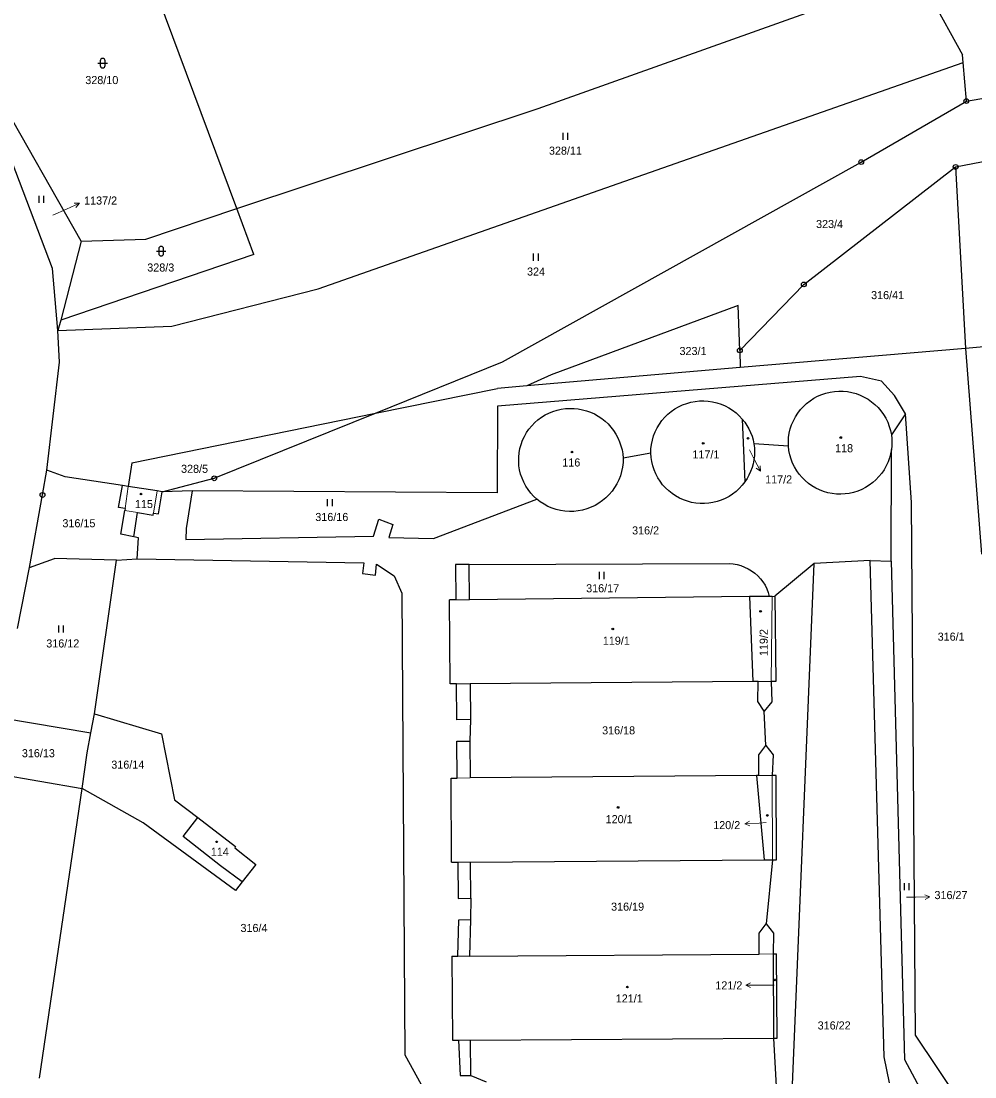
# Model space of a CAD drawing. Extents: x -765428 to -762163, y -1107632 to -1104975.
# Drawn here: x -763891.8 to -763690.9, y -1106861.1 to -1106638.7 of the extents above; entities that cross this region are included whole.
import ezdxf
from ezdxf.enums import TextEntityAlignment as Align

# ---------------------------------------------------------------- set-up
doc = ezdxf.new("R2010")
doc.units = 0
doc.header["$LTSCALE"] = 0.68
for name, color, linetype, lineweight in [('1', 7, 'Continuous', 25), ('3', 7, 'Continuous', 25), ('4', 7, 'Continuous', 13), ('5', 7, 'Continuous', 25), ('7', 7, 'Continuous', 13), ('8', 7, 'Continuous', 25)]:
    doc.layers.add(name, color=color, linetype=linetype, lineweight=lineweight)
doc.layers.add('2', color=7, linetype='Continuous')

msp = doc.modelspace()

# ---------------------------------------------------------------- linework, layer by layer
at = {"layer": '1'}
for p, q in [((-763846.36, -1106678.16), (-763869.74, -1106615.24)), ((-763782.87, -1106657.13), (-763702.97, -1106628.58)), ((-763702.97, -1106628.58), (-763693.52, -1106645.81)), ((-763885.2, -1106690.82), (-763903.89, -1106641.54)), ((-763879.14, -1106685.04), (-763903.89, -1106641.54)), ((-763693.39, -1106647.39), (-763693.52, -1106645.81)), ((-763770.01, -1106674.28), (-763693.39, -1106647.39)), ((-763692.69, -1106655.53), (-763693.39, -1106647.39)), ((-763692.69, -1106655.53), (-763674.07, -1106652.31)), ((-763714.83, -1106668.38), (-763692.69, -1106655.53)), ((-763846.36, -1106678.16), (-763782.87, -1106657.13)), ((-763694.94, -1106669.4), (-763676.21, -1106665.73)), ((-763790.41, -1106710.49), (-763714.83, -1106668.38)), ((-763726.92, -1106694.15), (-763694.94, -1106669.4)), ((-763694.94, -1106669.4), (-763692.84, -1106707.64)), ((-763829.2, -1106695.08), (-763770.01, -1106674.28)), ((-763865.55, -1106684.6), (-763846.36, -1106678.16)), ((-763842.75, -1106687.87), (-763846.36, -1106678.16)), ((-763879.14, -1106685.04), (-763865.55, -1106684.6)), ((-763879.14, -1106685.04), (-763883.43, -1106701.69)), ((-763842.75, -1106687.87), (-763883.43, -1106701.69)), ((-763884.08, -1106703.87), (-763885.2, -1106690.82)), ((-763860.01, -1106702.92), (-763829.2, -1106695.08)), ((-763740.4, -1106708.05), (-763726.92, -1106694.15)), ((-763740.75, -1106698.63), (-763780.11, -1106713.2)), ((-763740.4, -1106708.05), (-763740.75, -1106698.63)), ((-763883.43, -1106701.69), (-763884.08, -1106703.87)), ((-763884.08, -1106703.87), (-763860.01, -1106702.92)), ((-763883.68, -1106710.5), (-763884.08, -1106703.87)), ((-763684.15, -1106706.9), (-763692.84, -1106707.64)), ((-763740.4, -1106708.05), (-763740.31, -1106711.69)), ((-763692.84, -1106707.64), (-763740.31, -1106711.69)), ((-763692.84, -1106707.64), (-763689.53, -1106750.98)), ((-763886.36, -1106733.29), (-763883.68, -1106710.5)), ((-763817.15, -1106721.29), (-763790.41, -1106710.49)), ((-763714.95, -1106713.54), (-763791.44, -1106719.8)), ((-763740.31, -1106711.69), (-763785.28, -1106715.53)), ((-763780.11, -1106713.2), (-763785.28, -1106715.53)), ((-763710.56, -1106714.54), (-763714.95, -1106713.54)), ((-763817.15, -1106721.29), (-763791.43, -1106716.05)), ((-763785.28, -1106715.53), (-763791.43, -1106716.05)), ((-763707.84, -1106717.56), (-763710.56, -1106714.54)), ((-763705.49, -1106721.4), (-763707.84, -1106717.56)), ((-763791.44, -1106719.8), (-763791.48, -1106738.03)), ((-763868.45, -1106731.77), (-763817.15, -1106721.29)), ((-763851.1, -1106735), (-763817.15, -1106721.29)), ((-763739.88, -1106722.51), (-763739.35, -1106735.76)), ((-763705.49, -1106721.4), (-763708.48, -1106725.85)), ((-763704.22, -1106740.09), (-763705.49, -1106721.4)), ((-763730.16, -1106728.26), (-763737.42, -1106727.74)), ((-763708.52, -1106752.45), (-763708.47, -1106728.92)), ((-763759.16, -1106729.68), (-763764.98, -1106730.77)), ((-763887.28, -1106738.51), (-763886.36, -1106733.29)), ((-763882.5, -1106734.7), (-763886.36, -1106733.29)), ((-763868.45, -1106731.77), (-763869.21, -1106736.7)), ((-763870.45, -1106736.5), (-763882.5, -1106734.7)), ((-763862.05, -1106737.83), (-763851.1, -1106735)), ((-763871.26, -1106741.15), (-763870.45, -1106736.5)), ((-763869.21, -1106736.7), (-763870.45, -1106736.5)), ((-763863.13, -1106737.66), (-763869.21, -1106736.7)), ((-763862.05, -1106737.83), (-763863.13, -1106737.66)), ((-763862.87, -1106742.47), (-763862.05, -1106737.83)), ((-763855.75, -1106737.61), (-763862.05, -1106737.83)), ((-763855.75, -1106737.61), (-763857.03, -1106745.58)), ((-763791.48, -1106738.03), (-763855.75, -1106737.61)), ((-763890.05, -1106753.82), (-763887.28, -1106738.51)), ((-763804.89, -1106747.65), (-763783.17, -1106739.4)), ((-763703.4, -1106852.31), (-763704.22, -1106740.09)), ((-763869.88, -1106741.38), (-763871.26, -1106741.15)), ((-763870.76, -1106746.8), (-763869.95, -1106741.8)), ((-763869.88, -1106741.38), (-763869.95, -1106741.8)), ((-763868.05, -1106747.36), (-763867.28, -1106742.22)), ((-763867.28, -1106742.22), (-763863.98, -1106742.73)), ((-763863.98, -1106742.73), (-763863.91, -1106742.32)), ((-763863.91, -1106742.32), (-763862.87, -1106742.47)), ((-763817.54, -1106747.22), (-763816.46, -1106743.64)), ((-763816.46, -1106743.64), (-763813.52, -1106744.71)), ((-763813.52, -1106744.71), (-763814.34, -1106747.44)), ((-763868.05, -1106747.36), (-763870.76, -1106746.8)), ((-763857.03, -1106745.58), (-763857.08, -1106747.91)), ((-763857.08, -1106747.91), (-763817.54, -1106747.22)), ((-763867.03, -1106747.52), (-763868.05, -1106747.36)), ((-763867.36, -1106751.98), (-763867.03, -1106747.52)), ((-763814.34, -1106747.44), (-763804.89, -1106747.65)), ((-763892.53, -1106766.67), (-763890.05, -1106753.82)), ((-763890.05, -1106753.82), (-763884.76, -1106751.91)), ((-763871.69, -1106752.24), (-763884.76, -1106751.91)), ((-763876.32, -1106784.62), (-763871.69, -1106752.24)), ((-763871.69, -1106752.24), (-763867.36, -1106751.98)), ((-763867.36, -1106751.98), (-763819.63, -1106752.8)), ((-763819.63, -1106752.8), (-763819.89, -1106755.07)), ((-763817.17, -1106755.38), (-763816.91, -1106753.11)), ((-763816.91, -1106753.11), (-763813.24, -1106755.54)), ((-763797.42, -1106753.13), (-763800.32, -1106753.16)), ((-763800.32, -1106753.16), (-763800.25, -1106760.62)), ((-763797.42, -1106753.13), (-763742.64, -1106752.98)), ((-763797.35, -1106760.58), (-763797.42, -1106753.13)), ((-763724.72, -1106752.96), (-763733, -1106759.86)), ((-763729.84, -1106876.2), (-763724.72, -1106752.96)), ((-763712.98, -1106752.3), (-763724.72, -1106752.96)), ((-763709.99, -1106856.84), (-763712.98, -1106752.3)), ((-763712.98, -1106752.3), (-763708.52, -1106752.45)), ((-763708.52, -1106752.45), (-763705.7, -1106857.45)), ((-763819.89, -1106755.07), (-763817.17, -1106755.38)), ((-763813.24, -1106755.54), (-763811.58, -1106759.18)), ((-763811.58, -1106759.18), (-763810.93, -1106856.45)), ((-763738.38, -1106759.93), (-763797.35, -1106760.58)), ((-763734.2, -1106759.88), (-763738.38, -1106759.93)), ((-763738.38, -1106759.93), (-763737.66, -1106777.82)), ((-763733.6, -1106759.87), (-763734.2, -1106759.88)), ((-763733.6, -1106759.87), (-763733, -1106759.86)), ((-763733, -1106759.86), (-763732.82, -1106777.78)), ((-763800.25, -1106760.62), (-763801.52, -1106760.63)), ((-763801.39, -1106778.33), (-763801.52, -1106760.63)), ((-763800.09, -1106778.32), (-763801.39, -1106778.33)), ((-763800.01, -1106785.85), (-763800.09, -1106778.32)), ((-763737.66, -1106777.82), (-763797.18, -1106778.3)), ((-763797.18, -1106778.3), (-763797.11, -1106785.82)), ((-763736.56, -1106777.81), (-763737.66, -1106777.82)), ((-763736.64, -1106782.04), (-763736.56, -1106777.81)), ((-763732.82, -1106777.78), (-763733.78, -1106777.79)), ((-763733.78, -1106777.79), (-763733.66, -1106782.09)), ((-763735.29, -1106784.03), (-763736.64, -1106782.04)), ((-763733.66, -1106782.09), (-763735.29, -1106784.03)), ((-763877.07, -1106788.59), (-763876.32, -1106784.62)), ((-763876.32, -1106784.62), (-763862.24, -1106788.8)), ((-763734.93, -1106791.27), (-763735.29, -1106784.03)), ((-763895.86, -1106785.49), (-763877.07, -1106788.59)), ((-763797.11, -1106785.82), (-763800.01, -1106785.85)), ((-763797.11, -1106785.82), (-763797.28, -1106790.36)), ((-763877.87, -1106792.83), (-763877.07, -1106788.59)), ((-763862.24, -1106788.8), (-763859.47, -1106802.76)), ((-763799.98, -1106790.38), (-763797.28, -1106790.36)), ((-763799.92, -1106798.14), (-763799.98, -1106790.38)), ((-763797.28, -1106790.36), (-763797.23, -1106798.12)), ((-763736.41, -1106793.28), (-763734.93, -1106791.27)), ((-763734.93, -1106791.27), (-763733.41, -1106793.26)), ((-763878.91, -1106800.35), (-763877.87, -1106792.83)), ((-763736.38, -1106797.63), (-763736.41, -1106793.28)), ((-763733.41, -1106793.26), (-763733.62, -1106797.61)), ((-763898.11, -1106797.01), (-763878.91, -1106800.35)), ((-763801.23, -1106798.15), (-763799.92, -1106798.14)), ((-763801.13, -1106815.86), (-763801.23, -1106798.15)), ((-763736.87, -1106797.63), (-763797.23, -1106798.12)), ((-763736.87, -1106797.63), (-763735.26, -1106815.36)), ((-763736.38, -1106797.63), (-763736.87, -1106797.63)), ((-763732.78, -1106797.6), (-763733.62, -1106797.61)), ((-763732.66, -1106815.34), (-763732.78, -1106797.6)), ((-763887.93, -1106861.4), (-763878.91, -1106800.35)), ((-763866.11, -1106807.55), (-763878.91, -1106800.35)), ((-763859.47, -1106802.76), (-763854.56, -1106806.43)), ((-763857.63, -1106810.43), (-763854.56, -1106806.43)), ((-763854.56, -1106806.43), (-763846.6, -1106812.59)), ((-763846.63, -1106821.81), (-763866.11, -1106807.55)), ((-763849.79, -1106816.67), (-763857.63, -1106810.43)), ((-763846.6, -1106812.59), (-763846.79, -1106812.84)), ((-763846.79, -1106812.84), (-763842.34, -1106816.36)), ((-763801.13, -1106815.86), (-763799.8, -1106815.85)), ((-763799.8, -1106815.85), (-763799.75, -1106823.5)), ((-763797.1, -1106815.83), (-763735.26, -1106815.36)), ((-763797.04, -1106823.48), (-763797.1, -1106815.83)), ((-763735.26, -1106815.36), (-763733.54, -1106815.35)), ((-763733.54, -1106815.35), (-763734.86, -1106828.84)), ((-763733.54, -1106815.35), (-763732.66, -1106815.34)), ((-763845.25, -1106820.02), (-763849.79, -1106816.67)), ((-763842.34, -1106816.36), (-763845.25, -1106820.02)), ((-763845.25, -1106820.02), (-763846.63, -1106821.81)), ((-763799.75, -1106823.5), (-763797.04, -1106823.48)), ((-763797.04, -1106823.48), (-763797.14, -1106827.95)), ((-763799.8, -1106835.68), (-763799.58, -1106828.03)), ((-763799.58, -1106828.03), (-763797.14, -1106827.95)), ((-763797.14, -1106827.95), (-763797.31, -1106835.66)), ((-763736.35, -1106830.85), (-763734.86, -1106828.84)), ((-763734.86, -1106828.84), (-763733.34, -1106830.83)), ((-763736.3, -1106835.22), (-763736.35, -1106830.85)), ((-763733.34, -1106830.83), (-763733.4, -1106835.2)), ((-763801.06, -1106835.69), (-763799.8, -1106835.68)), ((-763801.06, -1106835.69), (-763800.91, -1106853.39)), ((-763797.31, -1106835.66), (-763736.3, -1106835.22)), ((-763733.4, -1106835.2), (-763732.71, -1106835.19)), ((-763733.4, -1106835.2), (-763733.28, -1106852.94)), ((-763732.54, -1106852.94), (-763732.71, -1106835.19)), ((-763800.91, -1106853.39), (-763799.64, -1106853.38)), ((-763799.64, -1106853.38), (-763799.3, -1106860.79)), ((-763797.14, -1106853.36), (-763733.28, -1106852.94)), ((-763797.08, -1106860.79), (-763797.14, -1106853.36)), ((-763733.28, -1106852.94), (-763732.54, -1106852.94)), ((-763733.28, -1106852.94), (-763732.61, -1106865.62)), ((-763652.64, -1106927.72), (-763703.4, -1106852.31)), ((-763810.93, -1106856.45), (-763806.76, -1106864.07)), ((-763708.89, -1106862.32), (-763709.99, -1106856.84)), ((-763705.7, -1106857.45), (-763702.02, -1106864.4)), ((-763799.3, -1106860.79), (-763797.08, -1106860.79)), ((-763797.08, -1106860.79), (-763793.86, -1106862.12))]:
    msp.add_line(p, q, dxfattribs=at)
for points in [[(-763730.16, -1106728.26), (-763730.181, -1106727.335), (-763730.124, -1106726.412), (-763729.989, -1106725.497), (-763729.777, -1106724.597), (-763729.489, -1106723.718), (-763729.128, -1106722.866), (-763728.696, -1106722.048), (-763728.197, -1106721.27), (-763727.634, -1106720.537), (-763727.01, -1106719.853), (-763726.331, -1106719.226), (-763725.601, -1106718.657), (-763724.826, -1106718.153), (-763724.011, -1106717.716), (-763723.161, -1106717.35), (-763722.284, -1106717.057), (-763721.385, -1106716.839), (-763720.471, -1106716.698), (-763719.549, -1106716.635), (-763718.624, -1106716.65), (-763717.704, -1106716.743), (-763716.795, -1106716.914), (-763715.904, -1106717.161), (-763715.036, -1106717.483), (-763714.2, -1106717.877), (-763713.399, -1106718.34), (-763712.641, -1106718.87), (-763711.93, -1106719.462), (-763711.272, -1106720.112), (-763710.671, -1106720.815), (-763710.132, -1106721.566), (-763709.658, -1106722.361), (-763709.254, -1106723.192), (-763708.921, -1106724.055), (-763708.662, -1106724.943), (-763708.48, -1106725.85)], [(-763783.17, -1106739.4), (-763783.836, -1106738.782), (-763784.449, -1106738.11), (-763785.003, -1106737.39), (-763785.494, -1106736.626), (-763785.92, -1106735.823), (-763786.278, -1106734.987), (-763786.564, -1106734.125), (-763786.777, -1106733.241), (-763786.916, -1106732.343), (-763786.979, -1106731.436), (-763786.965, -1106730.528), (-763786.876, -1106729.623), (-763786.712, -1106728.729), (-763786.473, -1106727.853), (-763786.162, -1106726.999), (-763785.78, -1106726.174), (-763785.331, -1106725.384), (-763784.817, -1106724.634), (-763784.242, -1106723.93), (-763783.611, -1106723.277), (-763782.927, -1106722.678), (-763782.195, -1106722.139), (-763781.421, -1106721.663), (-763780.61, -1106721.254), (-763779.767, -1106720.913), (-763778.899, -1106720.645), (-763778.011, -1106720.45), (-763777.11, -1106720.33)], [(-763777.11, -1106720.33), (-763776.216, -1106720.275), (-763775.321, -1106720.293), (-763774.43, -1106720.383), (-763773.55, -1106720.545), (-763772.685, -1106720.779), (-763771.843, -1106721.082), (-763771.028, -1106721.452), (-763770.245, -1106721.887), (-763769.5, -1106722.384), (-763768.799, -1106722.94), (-763768.144, -1106723.551), (-763767.542, -1106724.213), (-763766.995, -1106724.922), (-763766.508, -1106725.673), (-763766.083, -1106726.462), (-763765.723, -1106727.282), (-763765.432, -1106728.128), (-763765.21, -1106728.996), (-763765.059, -1106729.878), (-763764.98, -1106730.77)], [(-763759.16, -1106729.68), (-763759.126, -1106728.759), (-763759.015, -1106727.845), (-763758.827, -1106726.943), (-763758.564, -1106726.06), (-763758.228, -1106725.203), (-763757.821, -1106724.376), (-763757.346, -1106723.587), (-763756.806, -1106722.841), (-763756.206, -1106722.142), (-763755.549, -1106721.496), (-763754.84, -1106720.908), (-763754.084, -1106720.382), (-763753.287, -1106719.921), (-763752.453, -1106719.528), (-763751.59, -1106719.207), (-763750.703, -1106718.96), (-763749.798, -1106718.788), (-763748.882, -1106718.692), (-763747.961, -1106718.674), (-763747.042, -1106718.734), (-763746.131, -1106718.87), (-763745.234, -1106719.083), (-763744.359, -1106719.37), (-763743.511, -1106719.73), (-763742.696, -1106720.159), (-763741.92, -1106720.656), (-763741.189, -1106721.216), (-763740.507, -1106721.835), (-763739.88, -1106722.51)], [(-763739.88, -1106722.51), (-763739.362, -1106723.165), (-763738.896, -1106723.859), (-763738.484, -1106724.585), (-763738.128, -1106725.341), (-763737.831, -1106726.122), (-763737.595, -1106726.923), (-763737.42, -1106727.74)], [(-763708.48, -1106725.85), (-763708.399, -1106726.615), (-763708.37, -1106727.385), (-763708.394, -1106728.154), (-763708.47, -1106728.92)], [(-763737.42, -1106727.74), (-763737.327, -1106728.58), (-763737.299, -1106729.425), (-763737.336, -1106730.27), (-763737.438, -1106731.109), (-763737.604, -1106731.938), (-763737.833, -1106732.752), (-763738.125, -1106733.545), (-763738.476, -1106734.314), (-763738.885, -1106735.054), (-763739.35, -1106735.76)], [(-763708.47, -1106728.92), (-763708.632, -1106729.819), (-763708.868, -1106730.701), (-763709.177, -1106731.56), (-763709.557, -1106732.39), (-763710.005, -1106733.186), (-763710.518, -1106733.942), (-763711.093, -1106734.651), (-763711.725, -1106735.311), (-763712.409, -1106735.915), (-763713.142, -1106736.46), (-763713.918, -1106736.941), (-763714.731, -1106737.357), (-763715.576, -1106737.702), (-763716.448, -1106737.976), (-763717.339, -1106738.176), (-763718.243, -1106738.301), (-763719.155, -1106738.349), (-763720.068, -1106738.322), (-763720.975, -1106738.218), (-763721.871, -1106738.038), (-763722.748, -1106737.784), (-763723.601, -1106737.458), (-763724.423, -1106737.062), (-763725.21, -1106736.598), (-763725.955, -1106736.07), (-763726.653, -1106735.482), (-763727.3, -1106734.837), (-763727.891, -1106734.14), (-763728.421, -1106733.397), (-763728.887, -1106732.612), (-763729.286, -1106731.79), (-763729.615, -1106730.938), (-763729.871, -1106730.062), (-763730.053, -1106729.167), (-763730.16, -1106728.26)], [(-763764.98, -1106730.77), (-763765.007, -1106731.705), (-763765.113, -1106732.635), (-763765.297, -1106733.553), (-763765.558, -1106734.451), (-763765.894, -1106735.325), (-763766.302, -1106736.167), (-763766.78, -1106736.971), (-763767.324, -1106737.732), (-763767.931, -1106738.445), (-763768.595, -1106739.104), (-763769.313, -1106739.704), (-763770.079, -1106740.242), (-763770.887, -1106740.713), (-763771.733, -1106741.114), (-763772.609, -1106741.442), (-763773.51, -1106741.695), (-763774.429, -1106741.871), (-763775.359, -1106741.969), (-763776.295, -1106741.988), (-763777.229, -1106741.928), (-763778.154, -1106741.79), (-763779.064, -1106741.573), (-763779.953, -1106741.281), (-763780.814, -1106740.915), (-763781.641, -1106740.477), (-763782.428, -1106739.971), (-763783.17, -1106739.4)], [(-763739.35, -1106735.76), (-763739.909, -1106736.475), (-763740.526, -1106737.142), (-763741.196, -1106737.755), (-763741.915, -1106738.31), (-763742.677, -1106738.803), (-763743.478, -1106739.232), (-763744.311, -1106739.593), (-763745.171, -1106739.883), (-763746.053, -1106740.101), (-763746.949, -1106740.245), (-763747.855, -1106740.314), (-763748.763, -1106740.308), (-763749.667, -1106740.226), (-763750.562, -1106740.069), (-763751.44, -1106739.839), (-763752.296, -1106739.537), (-763753.125, -1106739.165), (-763753.919, -1106738.725), (-763754.674, -1106738.221), (-763755.385, -1106737.656), (-763756.046, -1106737.034), (-763756.654, -1106736.359), (-763757.203, -1106735.636), (-763757.691, -1106734.87), (-763758.113, -1106734.066), (-763758.467, -1106733.23), (-763758.751, -1106732.367), (-763758.961, -1106731.484), (-763759.098, -1106730.586), (-763759.16, -1106729.68)], [(-763742.64, -1106752.98), (-763741.804, -1106753.04), (-763740.978, -1106753.179), (-763740.168, -1106753.395), (-763739.382, -1106753.686), (-763738.627, -1106754.05), (-763737.91, -1106754.483), (-763737.237, -1106754.983), (-763736.614, -1106755.543), (-763736.046, -1106756.16), (-763735.539, -1106756.827), (-763735.098, -1106757.54), (-763734.725, -1106758.29), (-763734.425, -1106759.073), (-763734.2, -1106759.88)]]:
    msp.add_lwpolyline(points, dxfattribs=at)
at = {"layer": '3'}
for p, q in [((-763875.111, -1106647.041), (-763875.111, -1106648.042)), ((-763874.109, -1106648.042), (-763874.109, -1106647.041)), ((-763875.611, -1106647.541), (-763873.609, -1106647.541)), ((-763777.641, -1106663.7), (-763777.641, -1106662.2)), ((-763776.64, -1106663.7), (-763776.64, -1106662.2)), ((-763887.991, -1106676.97), (-763887.991, -1106675.47)), ((-763886.99, -1106676.97), (-763886.99, -1106675.47)), ((-763863.291, -1106687.151), (-763861.289, -1106687.151)), ((-763862.791, -1106686.651), (-763862.791, -1106687.652)), ((-763861.789, -1106687.652), (-763861.789, -1106686.651)), ((-763783.841, -1106689.17), (-763783.841, -1106687.67)), ((-763782.84, -1106689.17), (-763782.84, -1106687.67)), ((-763827.231, -1106740.87), (-763827.231, -1106739.37)), ((-763826.23, -1106740.87), (-763826.23, -1106739.37)), ((-763769.981, -1106756.22), (-763769.981, -1106754.72)), ((-763768.98, -1106756.22), (-763768.98, -1106754.72)), ((-763883.841, -1106767.51), (-763883.841, -1106766.01)), ((-763882.84, -1106767.51), (-763882.84, -1106766.01)), ((-763705.731, -1106821.78), (-763705.731, -1106820.28)), ((-763704.73, -1106821.78), (-763704.73, -1106820.28))]:
    msp.add_line(p, q, dxfattribs=at)
for centre, start, end in [((-763874.61, -1106647.0409), 0, 180), ((-763874.61, -1106648.0409), 180, 359.98789), ((-763862.29, -1106686.6509), 0, 180), ((-763862.29, -1106687.6509), 180, 359.98789)]:
    msp.add_arc(centre, 0.5, start, end, dxfattribs=at)
at = {"layer": '4'}
for p, q in [((-763869.21, -1106736.7), (-763869.88, -1106741.38)), ((-763863.13, -1106737.66), (-763863.91, -1106742.32)), ((-763867.28, -1106742.22), (-763869.95, -1106741.8)), ((-763800.25, -1106760.62), (-763797.35, -1106760.58)), ((-763733.78, -1106777.79), (-763733.6, -1106759.87)), ((-763800.09, -1106778.32), (-763797.18, -1106778.3)), ((-763733.78, -1106777.79), (-763736.56, -1106777.81)), ((-763797.23, -1106798.12), (-763799.92, -1106798.14)), ((-763733.62, -1106797.61), (-763736.38, -1106797.63)), ((-763733.62, -1106797.61), (-763733.54, -1106815.35)), ((-763797.1, -1106815.83), (-763799.8, -1106815.85)), ((-763799.8, -1106835.68), (-763797.31, -1106835.66)), ((-763733.4, -1106835.2), (-763736.3, -1106835.22)), ((-763799.64, -1106853.38), (-763797.14, -1106853.36))]:
    msp.add_line(p, q, dxfattribs=at)
at = {"layer": '5'}
for centre in [(-763738.6768, -1106726.5792), (-763719.1268, -1106726.4092), (-763775.7668, -1106729.4692), (-763748.1068, -1106727.6392), (-763866.5268, -1106738.3092), (-763736.0368, -1106763.0192), (-763767.1568, -1106766.7392), (-763766.0368, -1106804.3292), (-763734.6168, -1106806.0192), (-763850.5868, -1106811.5792), (-763732.9768, -1106840.6592), (-763764.0868, -1106842.1692)]:
    msp.add_circle(centre, 0.175, dxfattribs=at)
at = {"layer": '7'}
for p, q in [((-763879.518, -1106677.059), (-763880.637, -1106677.009)), ((-763736.078, -1106733.524), (-763736.086, -1106732.404)), ((-763739.317, -1106807.777), (-763738.291, -1106808.225)), ((-763700.399, -1106823.198), (-763701.41, -1106822.714)), ((-763739.131, -1106841.78), (-763738.13, -1106842.281))]:
    msp.add_line(p, q, dxfattribs=at)
for points in [[(-763885.13, -1106679.57), (-763882.26, -1106678.28), (-763879.518, -1106677.059), (-763880.23, -1106677.924)], [(-763738.39, -1106728.98), (-763737.44, -1106730.85), (-763736.078, -1106733.524), (-763736.978, -1106732.859)], [(-763734.84, -1106807.54), (-763736.32, -1106807.62), (-763739.317, -1106807.777), (-763738.343, -1106807.225)], [(-763705.32, -1106823.27), (-763703.4, -1106823.25), (-763700.399, -1106823.198), (-763701.392, -1106823.716)], [(-763733.14, -1106841.76), (-763736.13, -1106841.78), (-763739.131, -1106841.78), (-763738.13, -1106841.279)]]:
    msp.add_lwpolyline(points, dxfattribs=at)
at = {"layer": '8'}
for centre, radius in [((-763692.69, -1106655.5299), 0.5), ((-763692.69, -1106655.5299), 0.0303), ((-763714.83, -1106668.3799), 0.5), ((-763714.83, -1106668.3799), 0.0303), ((-763694.94, -1106669.3999), 0.5), ((-763694.94, -1106669.3999), 0.0303), ((-763726.92, -1106694.1499), 0.5), ((-763726.92, -1106694.1499), 0.0303), ((-763740.4, -1106708.0499), 0.5), ((-763740.4, -1106708.0499), 0.0303), ((-763851.1, -1106734.9999), 0.5), ((-763851.1, -1106734.9999), 0.0303), ((-763887.28, -1106738.5099), 0.5), ((-763887.28, -1106738.5099), 0.0303)]:
    msp.add_circle(centre, radius, dxfattribs=at)

# ---------------------------------------------------------------- texts
at = {"layer": '2'}
for s, p in [('328/10', (-763874.79, -1106651.955)), ('328/11', (-763777.13, -1106666.825)), ('323/4', (-763721.5, -1106682.285)), ('328/3', (-763862.37, -1106691.445)), ('324', (-763783.329, -1106692.295)), ('323/1', (-763750.26, -1106709.035)), ('116', (-763775.899, -1106732.515))]:
    msp.add_text(s, height=1.7, dxfattribs=at).set_placement(p, align=Align.CENTER)
for s, p in [('1137/2', (-763878.52, -1106677.335)), ('316/41', (-763712.75, -1106697.255)), ('117/1', (-763750.39, -1106730.825)), ('118', (-763720.34, -1106729.505)), ('328/5', (-763858.1, -1106733.845)), ('117/2', (-763735.07, -1106736.085)), ('115', (-763867.81, -1106741.265)), ('316/16', (-763829.82, -1106743.995)), ('316/15', (-763883.09, -1106745.315)), ('316/2', (-763763.1, -1106746.825)), ('316/17', (-763772.77, -1106759.015)), ('316/12', (-763886.49, -1106770.635)), ('119/1', (-763769.26, -1106770.055)), ('316/1', (-763698.73, -1106769.205)), ('316/18', (-763769.41, -1106788.945)), ('316/13', (-763891.63, -1106793.755)), ('316/14', (-763872.79, -1106796.165)), ('120/1', (-763768.66, -1106807.655)), ('114', (-763851.83, -1106814.525)), ('316/27', (-763699.4, -1106823.645)), ('316/19', (-763767.52, -1106826.085)), ('316/4', (-763845.58, -1106830.575)), ('121/1', (-763766.53, -1106845.425)), ('316/22', (-763724.01, -1106851.105))]:
    msp.add_text(s, height=1.7, dxfattribs=at).set_placement(p)
msp.add_text('119/2', height=1.7, rotation=90, dxfattribs=at).set_placement((-763734.525, -1106769.6), align=Align.CENTER)
for s, p in [('120/2', (-763740.32, -1106808.905)), ('121/2', (-763739.87, -1106842.665))]:
    msp.add_text(s, height=1.7, dxfattribs=at).set_placement(p, align=Align.RIGHT)

doc.saveas('drawing.dxf')
